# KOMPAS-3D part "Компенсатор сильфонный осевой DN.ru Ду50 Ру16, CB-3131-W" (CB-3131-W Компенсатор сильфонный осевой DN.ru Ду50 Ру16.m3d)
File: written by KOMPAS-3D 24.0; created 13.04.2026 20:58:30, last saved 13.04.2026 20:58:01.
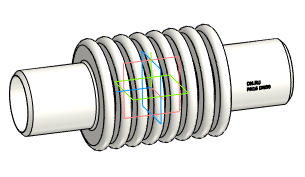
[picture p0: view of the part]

Document properties: Автор: DN.RU; Полное имя файла: D:\PROJECT CAD\DN.RU\...197(ACTUALE). CB-3131-W Компенсатор сильфонный осевой DN.ru\Исходники\DN50\CB-3131-W Компенсатор сильфонный осевой DN.ru Ду50 Ру16.m3d

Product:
- Body: Твердое тело1  | qty 1
    Масса: 1.40197
- Part/product: Компенсатор сильфонный осевой DN.ru Ду50 Ру16  | designation CB-3131-W
    Масса: 0.6
    Раздел спецификации: Прочие изделия
    Комментарий: D140-02130
    Примечание: D140-02130
    additional columns: Типовые

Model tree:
1. Твердое тело1  (labels: Твердое тело1)

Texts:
  CB-3131-W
